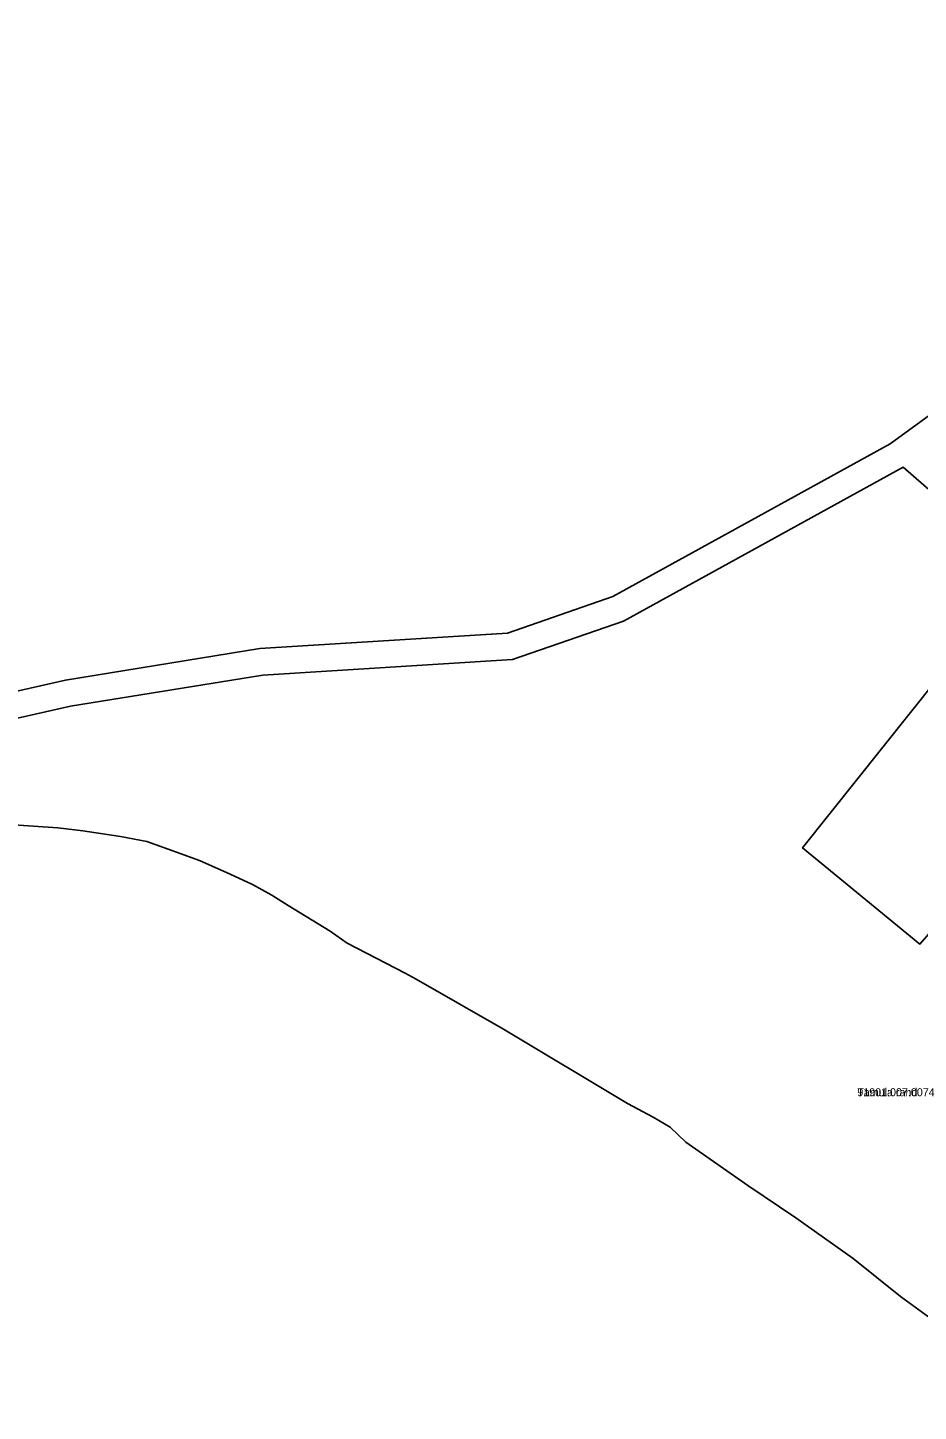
# Model space of a CAD drawing. Extents: x 675810 to 681273, y 6411190 to 6417565.
# Drawn here: x 677035.3 to 677202.3, y 6415518.6 to 6415777.9 of the extents above; entities that cross this region are included whole.
import ezdxf

# ---------------------------------------------------------------- set-up
doc = ezdxf.new("R2010")
doc.units = 0
for name, color, linetype in [('L_AADRESS', 7, 'Continuous'), ('PIIR', 7, 'Continuous'), ('TUNNUS', 7, 'Continuous')]:
    doc.layers.add(name, color=color, linetype=linetype)

msp = doc.modelspace()

# ---------------------------------------------------------------- linework, layer by layer
at = {"layer": 'PIIR'}
for points in [[(677207.34, 6415789.22), (677214.24, 6415765.69), (677234.9, 6415740.29), (677266.19, 6415769.85), (677270.85, 6415765.21), (677262.26, 6415758.1), (677244.69, 6415739.98), (677227.13, 6415721.86), (677196.99, 6415699.93), (677144.99, 6415671.31), (677125.24, 6415664.48), (677102.03, 6415663.02), (677078.82, 6415661.56), (677042.4, 6415655.67), (677021.12, 6415650.85)], [(677021.12, 6415650.85), (677042.4, 6415655.67), (677078.82, 6415661.56), (677125.24, 6415664.48), (677144.99, 6415671.31), (677196.99, 6415699.93), (677227.13, 6415721.86)], [(677206.7, 6415689.28), (677199.4, 6415695.55), (677147.03, 6415666.72), (677126.23, 6415659.53), (677079.38, 6415656.59), (677043.35, 6415650.76), (677001.4, 6415641.26)], [(677001.4, 6415641.26), (677043.35, 6415650.76), (677079.38, 6415656.59), (677126.23, 6415659.53), (677147.03, 6415666.72), (677199.4, 6415695.55), (677206.7, 6415689.28)], [(677205.71, 6415655.76), (677180.56, 6415624.22), (677202.58, 6415606.2)], [(677032.74, 6415628.53), (677040.96, 6415627.97), (677045.65, 6415627.44), (677052.71, 6415626.36), (677057.65, 6415625.39), (677063.25, 6415623.45), (677067.53, 6415621.83), (677073.3, 6415619.3), (677077.5, 6415617.35), (677081.07, 6415615.39), (677084.13, 6415613.41), (677092.05, 6415608.62), (677095.19, 6415606.38), (677106.11, 6415600.76), (677108.13, 6415599.6), (677124.53, 6415590.26), (677147.73, 6415576.32), (677152.58, 6415573.76), (677155.76, 6415571.91), (677158.67, 6415569.09), (677170.31, 6415560.97), (677179.3, 6415554.89), (677190.06, 6415547.3), (677198.9, 6415540.15), (677228.48, 6415518.63)], [(677228.48, 6415518.63), (677198.9, 6415540.15), (677190.06, 6415547.3), (677179.3, 6415554.89), (677170.31, 6415560.97), (677158.67, 6415569.09), (677155.76, 6415571.91), (677152.58, 6415573.76), (677147.73, 6415576.32), (677124.53, 6415590.26), (677108.13, 6415599.6), (677106.11, 6415600.76), (677095.19, 6415606.38), (677092.05, 6415608.62), (677084.13, 6415613.41), (677081.07, 6415615.39), (677077.5, 6415617.35), (677073.3, 6415619.3), (677067.53, 6415621.83), (677063.25, 6415623.45), (677057.65, 6415625.39), (677052.71, 6415626.36), (677045.65, 6415627.44), (677040.96, 6415627.97), (677032.74, 6415628.53)]]:
    msp.add_lwpolyline(points, dxfattribs=at)
msp.add_lwpolyline([(677205.71, 6415655.76), (677251.48, 6415617), (677238.1, 6415601.8), (677215.57, 6415621.08), (677202.58, 6415606.2), (677180.56, 6415624.22)], close=True, dxfattribs=at)

# ---------------------------------------------------------------- texts
at = {"layer": 'L_AADRESS'}
msp.add_text('Tamula rand', height=1.5, dxfattribs=at).set_placement((677190.83, 6415577.68))
at = {"layer": 'TUNNUS'}
msp.add_text('91901:007:0074', height=1.5, dxfattribs=at).set_placement((677190.83, 6415577.68))

doc.saveas('drawing.dxf')
